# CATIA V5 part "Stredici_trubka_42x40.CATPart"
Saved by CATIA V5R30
Part number: Stredici_trubka_42x40
Definition: E 1160_42x40_3
Nomenclature: E 1160_42x40_3
Source: Unknown
Description: PART--DESC
Bounding box of the stored display mesh (mm): x -208 to -166, y -157.99 to -116.01, z 90.7 to 130.7
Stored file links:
  E:\Bakalarka\Model\Forma_v7\Stredici_trubka_42x40.CATPart
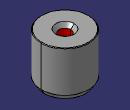
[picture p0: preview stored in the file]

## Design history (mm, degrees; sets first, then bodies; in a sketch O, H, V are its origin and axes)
Body1 "MANIFOLD_SOLID_BREP #3850" (main body)
  Solid1: solid without history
